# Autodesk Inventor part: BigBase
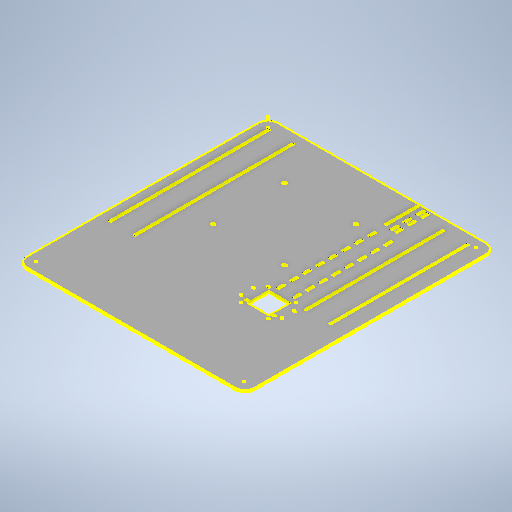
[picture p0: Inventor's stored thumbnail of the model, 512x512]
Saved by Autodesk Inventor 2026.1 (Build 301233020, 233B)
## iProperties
Created: 2026-10
Part Number: BigBase
Material: Generic
Document SubType Name: Modeling
Designer: hp
Density: 1 g/cm^3
Appearance: Default
Author: hp
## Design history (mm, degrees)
sketch "BigBaseSketch"
  geometry: L1 (0, 0)-(1200, 0); L2 (1200, 0)-(1200, 700); L3 (1200, 700)-(0, 700); L4 (0, 700)-(0, 0); L5 (378, 191.5)-(141, 191.5); L6 (141, 191.5)-(141, 428.5); L7 (141, 428.5)-(378, 428.5); L8 (378, 428.5)-(378, 191.5); L9 (378, 191.5)-(141, 428.5); L10 (141, 191.5)-(378, 428.5); L11 (259.5, 191.5)-(259.5, 428.5); L12 (378, 310)-(141, 310); L13 (141, 310)-(378, 310); C1 r 5 at (150, 200.5); C2 r 5 at (150, 419.5); C3 r 5 at (369, 200.5); C4 r 5 at (369, 419.5); 1 further point
  constraints: 26 end point, 5 midpoint, 5 symmetric about line, 4 centre point, 4 parallel, 2 horizontal, 2 perpendicular, 1 point on line, 3 other
  dimensions: "d0" = 1200 distance of L3.end L2.end; "d236" = 237 distance of L6.end L7.end; "d237" = 237 distance of L5.end L6.end; "d242" = 10 diameter of C1; "d243" = 9 distance from line of L5 C1.centre; "d245" = 150 distance from line of L4 C1.centre; "d252" = 700 distance of L3.end L1.start; "d253" = 40 vertical distance of point (0, 350) L12.end
extrude "Extrusion2" new body sketch "BigBaseSketch" distance "d14" = 5; taper "d15" = 0 deg
sketch "Sketch3"
  geometry: L1 (31, -10)-(31, 630); L2 (31, 106.5)-(521, 106.5); L3 (521, 106.5)-(521, 111.5); L4 (521, 111.5)-(31, 111.5); L5 (31, 111.5)-(31, 106.5); L6 (31, 31.5)-(521, 31.5); L7 (521, 31.5)-(521, 36.5); L8 (521, 36.5)-(31, 36.5); L9 (31, 36.5)-(31, 31.5); L10 (31, 568.5)-(456, 568.5); L11 (456, 568.5)-(456, 573.5); L12 (456, 573.5)-(31, 573.5); L13 (31, 573.5)-(31, 568.5); L14 (31, 643.5)-(456, 643.5); L15 (456, 648.5)-(31, 648.5); L16 (456, 643.5)-(456, 648.5); L17 (31, 648.5)-(31, 643.5); L18 (378, 191.5)-(141, 191.5) reference; L19 (141, 191.5)-(141, 428.5) reference; L20 (141, 428.5)-(378, 428.5) reference; L21 (378, 428.5)-(378, 191.5) reference; L22 (259.5, 191.5)-(259.5, 428.5) reference; L23 (0, 700)-(0, 0) reference; L24 (131, 468.5)-(461, 468.5); L25 (461, 468.5)-(461, 523.5); L26 (461, 523.5)-(131, 523.5); L27 (131, 523.5)-(131, 468.5); L28 (131, 468.5)-(461, 468.5); L29 (461, 468.5)-(461, 473.5); L30 (461, 473.5)-(131, 473.5); L31 (131, 473.5)-(131, 468.5); L32 (131, 523.5)-(461, 523.5); L33 (461, 523.5)-(461, 518.5); L34 (461, 518.5)-(131, 518.5); L35 (131, 518.5)-(131, 523.5); 3 further points; 2 other entities
  constraints: 58 end point, 14 parallel, 7 horizontal, 7 perpendicular, 4 collinear, 2 midpoint, 2 point on line, 1 horizontal alignment, 2 other
  dimensions: "d64" = 640 distance of L1.end L1.start; "d129" = 490 distance of L4.end L3.end; "d130" = 5 distance of L3.end L2.end; "d133" = 490 distance of L8.end L7.end (derived); "d134" = 5 distance of L7.end L6.end; "d135" = 70 distance between parallel lines of L2 L8; "d138" = 425 distance of L12.end L11.end; "d139" = 5 distance of L11.end L10.end; "d140" = 425 distance of L15.end L15.start (derived); "d141" = 5 distance of L15.start L14.end; "d144" = 70 distance between parallel lines of L12 L14; "d248" = 80 distance between parallel lines of L4 L18; "d249" = 140 distance between parallel lines of L20 L10; "d251" = 31 distance between parallel lines of L1 L23; "d259" = 330 distance of L26.end L25.end; "d260" = 55 distance of L25.end L24.end; "d261" = 40 distance between parallel lines of L20 L24; "d262" = 5 distance between parallel lines of L11 L25; "d263" = 5 distance of L29.end L28.end; "d264" = 5 distance of L32.end L33.end
extrude "Extrusion3" cut sketch "Sketch3" extent not by distance; stored distance "d101" = 0; taper "d102" = 0 deg
sketch "Sketch20"
  geometry: 4 further points
hole "Hole8" sketch "Sketch20" at (-477, 433.5), (-515, 433.5), (-477, 558.5), (-515, 558.5) diameter "d331" = 4.5; stored, may be unused: countersink angle "d335" = 90 deg, drill point angle "d337" = 0 deg; dims "d332" = 6, "d333" = 4, "d334" = 2, "d336" = 8
sketch "Sketch4"
  geometry: L1 (526, 463.5)-(526, 528.5); L2 (526, 528.5)-(461, 528.5); L3 (461, 528.5)-(461, 463.5); L4 (461, 463.5)-(526, 463.5); L5 (378, 428.5)-(378, 191.5) reference; L6 (378, 191.5)-(141, 191.5) reference; L7 (461, 468.5)-(461, 523.5) reference; 1 further point
  constraints: 8 end point, 2 parallel, 1 perpendicular
  dimensions: "d119" = 65 distance of L3.end L2.end; "d120" = 65 distance of L2.end L1.end; "d330" = 83 distance between parallel lines of L5 L3
extrude "Extrusion4" cut sketch "Sketch4" extent not by distance; stored distance "d112" = 0; taper "d113" = 0 deg
fillet "Fillet1" dims "d147" = 30
extrude "Extrusion7" cut sketch "BigBaseSketch" distance "d246" = 5; taper "d247" = 0 deg
sketch "Sketch16"
  geometry: L1 (131, 468.5)-(461, 468.5) reference; L2 (461, 473.5)-(131, 473.5) reference; L3 (461, 518.5)-(131, 518.5) reference; L4 (131, 523.5)-(461, 523.5) reference; L5 (131, 523.5)-(131, 468.5) reference; L6 (461, 468.5)-(461, 523.5) reference; L7 (141, 468.5)-(161, 468.5); L8 (161, 468.5)-(161, 473.5); L9 (161, 473.5)-(141, 473.5); L10 (141, 473.5)-(141, 468.5); L11 (141, 518.5)-(161, 518.5); L12 (161, 518.5)-(161, 523.5); L13 (161, 523.5)-(141, 523.5); L14 (141, 523.5)-(141, 518.5); L15 (181, 473.5)-(181, 468.5); L16 (181, 468.5)-(201, 468.5); L17 (201, 473.5)-(181, 473.5); L18 (201, 468.5)-(201, 473.5); L19 (181, 518.5)-(201, 518.5); L20 (181, 523.5)-(181, 518.5); L21 (201, 518.5)-(201, 523.5); L22 (201, 523.5)-(181, 523.5); L23 (221, 473.5)-(221, 468.5); L24 (221, 468.5)-(241, 468.5); L25 (241, 473.5)-(221, 473.5); L26 (241, 468.5)-(241, 473.5); L27 (221, 518.5)-(241, 518.5); L28 (221, 523.5)-(221, 518.5); L29 (241, 518.5)-(241, 523.5); L30 (241, 523.5)-(221, 523.5); L31 (261, 473.5)-(261, 468.5); L32 (261, 468.5)-(281, 468.5); L33 (281, 473.5)-(261, 473.5); L34 (281, 468.5)-(281, 473.5); L35 (261, 518.5)-(281, 518.5); L36 (261, 523.5)-(261, 518.5); L37 (281, 518.5)-(281, 523.5); L38 (281, 523.5)-(261, 523.5); L39 (301, 473.5)-(301, 468.5); L40 (301, 468.5)-(321, 468.5); L41 (321, 473.5)-(301, 473.5); L42 (321, 468.5)-(321, 473.5); L43 (301, 518.5)-(321, 518.5); L44 (301, 523.5)-(301, 518.5); L45 (321, 518.5)-(321, 523.5); L46 (321, 523.5)-(301, 523.5); L47 (341, 473.5)-(341, 468.5); L48 (341, 468.5)-(361, 468.5); L49 (361, 473.5)-(341, 473.5); L50 (361, 468.5)-(361, 473.5); L51 (341, 518.5)-(361, 518.5); L52 (341, 523.5)-(341, 518.5); L53 (361, 518.5)-(361, 523.5); L54 (361, 523.5)-(341, 523.5); L55 (381, 473.5)-(381, 468.5); L56 (381, 468.5)-(401, 468.5); L57 (401, 473.5)-(381, 473.5); L58 (401, 468.5)-(401, 473.5); L59 (381, 518.5)-(401, 518.5); L60 (381, 523.5)-(381, 518.5); L61 (401, 518.5)-(401, 523.5); L62 (401, 523.5)-(381, 523.5); L63 (421, 473.5)-(421, 468.5); L64 (421, 468.5)-(441, 468.5)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; 1 further point
  constraints: 128 end point, 4 parallel, 4 point on line, 3 horizontal, 2 perpendicular, 1 collinear, 112 other
  dimensions: "d274" = 20 distance of L9.end L8.end; "d275" = 10 distance between parallel lines of L5 L10; "d276" = 20 distance of L13.end L12.end; "d279" = 40 distance of L7.start L15.end
extrude "Extrusion8" cut sketch "Sketch16" distance "d284" = 5; taper "d285" = 0 deg
sketch "Sketch17"
  geometry: L1 (461, 528.5)-(526, 528.5) reference; L2 (461, 463.5)-(461, 528.5) reference; L3 (526, 528.5)-(526, 463.5) reference; L4 (526, 463.5)-(461, 463.5) reference; L5 (1170, 700)-(30, 700) reference; L6 (461, 700)-(526, 700); L7 (526, 700)-(526, 800); L8 (526, 800)-(461, 800); L9 (461, 800)-(461, 700); L10 (491.3, 590)-(498.5, 590); L11 (498.5, 590)-(498.5, 767); L12 (498.5, 767)-(491.3, 767); L13 (491.3, 767)-(491.3, 590); L14 (0, 492.4)-(121, 492.4); L15 (121, 492.4)-(121, 499.6); L16 (121, 499.6)-(0, 499.6); L17 (0, 499.6)-(0, 492.4); L18 (131, 523.5)-(131, 468.5) reference; L19 (0, 670)-(0, 30) reference; L20 (0, 499.6)-(121, 499.6); L21 (121, 499.6)-(121, 505.6); L22 (121, 505.6)-(0, 505.6); L23 (0, 505.6)-(0, 499.6); L24 (0, 492.4)-(121, 492.4); L25 (121, 492.4)-(121, 486.4); L26 (121, 486.4)-(0, 486.4); L27 (0, 486.4)-(0, 492.4); 6 further points
  constraints: 40 end point, 10 parallel, 5 horizontal, 5 perpendicular, 4 midpoint, 3 point on line, 1 collinear, 1 horizontal alignment
  dimensions: "d288" = 100 distance of L7.end L6.end; "d291" = 7.2 distance of L12.end L11.end; "d294" = 33 distance between parallel lines of L8 L12; "d295" = 210 distance from line of point (493.5, 800) L10; "d298" = 31.1 distance from line of L3 point (494.9, 590) (derived); "d306" = 7.2 distance of L15.end L14.end; "d307" = 10 distance of point (131, 496) point (121, 496); "d308" = 6 distance of L21.end L20.end; "d309" = 6 distance of L24.end L25.end (derived)
sketch "Sketch19"
  geometry: L1 (0, 670)-(0, 30) reference; L2 (121, 486.4)-(0, 486.4) reference; L3 (121, 505.6)-(0, 505.6) reference; L4 (121, 499.6)-(0, 499.6) reference; L5 (0, 492.4)-(121, 492.4) reference; L6 (121, 492.4)-(121, 486.4) reference; L7 (121, 499.6)-(121, 505.6) reference; L8 (10, 486.4)-(30, 486.4); L9 (30, 486.4)-(30, 492.4); L10 (30, 492.4)-(10, 492.4); L11 (10, 492.4)-(10, 486.4); L12 (10, 499.6)-(30, 499.6); L13 (30, 499.6)-(30, 505.6); L14 (30, 505.6)-(10, 505.6); L15 (10, 505.6)-(10, 499.6); L16 (10.1, 486.4)-(29.9, 486.4); L17 (29.9, 486.4)-(29.9, 492.4); L18 (29.9, 492.4)-(10.1, 492.4); L19 (10.1, 492.4)-(10.1, 486.4); L20 (10.1, 499.6)-(29.9, 499.6); L21 (29.9, 499.6)-(29.9, 505.6); L22 (29.9, 505.6)-(10.1, 505.6); L23 (10.1, 505.6)-(10.1, 499.6); L24 (50.1, 492.4)-(50.1, 486.4); L25 (50.1, 486.4)-(69.9, 486.4); L26 (50, 492.4)-(50, 486.4); L27 (50, 486.4)-(70, 486.4); L28 (69.9, 499.6)-(69.9, 505.6); L29 (70, 499.6)-(70, 505.6); L30 (69.9, 492.4)-(50.1, 492.4); L31 (70, 492.4)-(50, 492.4); L32 (50.1, 499.6)-(69.9, 499.6); L33 (50, 499.6)-(70, 499.6); L34 (69.9, 505.6)-(50.1, 505.6); L35 (70, 505.6)-(50, 505.6); L36 (50.1, 505.6)-(50.1, 499.6); L37 (50, 505.6)-(50, 499.6); L38 (69.9, 486.4)-(69.9, 492.4); L39 (70, 486.4)-(70, 492.4); L40 (90.1, 492.4)-(90.1, 486.4); L41 (90.1, 486.4)-(109.9, 486.4); L42 (90, 492.4)-(90, 486.4); L43 (90, 486.4)-(110, 486.4); L44 (109.9, 499.6)-(109.9, 505.6); L45 (110, 499.6)-(110, 505.6); L46 (109.9, 492.4)-(90.1, 492.4); L47 (110, 492.4)-(90, 492.4); L48 (90.1, 499.6)-(109.9, 499.6); L49 (90, 499.6)-(110, 499.6); L50 (109.9, 505.6)-(90.1, 505.6); L51 (110, 505.6)-(90, 505.6); L52 (90.1, 505.6)-(90.1, 499.6); L53 (90, 505.6)-(90, 499.6); L54 (109.9, 486.4)-(109.9, 492.4); L55 (110, 486.4)-(110, 492.4); 13 further points
  constraints: 96 end point, 8 parallel, 8 point on line, 5 horizontal, 4 midpoint, 4 perpendicular, 3 collinear, 2 coincident, 71 other
  dimensions: "d310" = 20 distance of L10.end L9.end; "d311" = 10 distance between parallel lines of L1 L11; "d321" = 19.8 distance of L18.end L17.end; "d322" = 19.8 distance of L22.end L21.end; "d325" = 40 distance of point (20, 492.4) point (60, 492.4)
extrude "Extrusion11" cut sketch "Sketch19" stored distance "d319" = 10; taper "d320" = 0 deg
sketch "Sketch21"
  geometry: L1 (1170, 700)-(30, 700) reference; L2 (1201.62, 0)-(771, 0); L3 (771, 0)-(771, 700); L4 (771, 700)-(1201.62, 700); L5 (1201.62, 700)-(1201.62, 0); L6 (521, 111.5)-(521, 106.5) reference; 2 further points
  constraints: 8 end point, 2 parallel, 1 horizontal, 1 perpendicular, 1 point on line
  dimensions: "d340" = 250 distance between parallel lines of L3 L6
extrude "Extrusion12" cut sketch "Sketch21" distance "d338" = 10; taper "d339" = 0 deg
fillet "Fillet2" dims "d341" = 30
sketch "Sketch22"
  geometry: L1 (5, 464.5)-(105, 464.5); L2 (105, 464.5)-(105, 469.5); L3 (105, 469.5)-(5, 469.5); L4 (5, 469.5)-(5, 464.5); L5 (0, 670)-(0, 30) reference; L6 (29.9, 486.4)-(10.1, 486.4) reference; 2 further points
  constraints: 8 end point, 2 parallel, 1 horizontal, 1 midpoint, 1 perpendicular
  dimensions: "d342" = 100 distance of L3.end L2.end; "d343" = 5 distance of L2.end L1.end; "d344" = 5 distance from line of L5 point (5, 467); "d345" = 16.9 distance between parallel lines of L6 L3
extrude "Extrusion13" cut sketch "Sketch22" distance "d346" = 5; taper "d347" = 0 deg
sketch "Sketch23"
  geometry: 4 further points
hole "Hole9" sketch "Sketch23" at (536, 538.5), (451, 538.5), (451, 453.5), (536, 453.5) diameter "d348" = 4.5; stored, may be unused: countersink angle "d352" = 90 deg, drill point angle "d354" = 0 deg; dims "d349" = 6, "d350" = 4, "d351" = 2, "d353" = 8
sketch "Sketch24"
  geometry: L1 (-105, 469.5)-(-5, 469.5) reference; L2 (-5, 469.5)-(-5, 464.5) reference; L3 (-5, 464.5)-(-105, 464.5) reference; L4 (-105, 464.5)-(-105, 469.5) reference; L5 (-771, 670)-(-771, 30) reference; L6 (-30, 0)-(-741, 0) reference; L7 (0, 670)-(0, 30) reference; L8 (-741, 700)-(-30, 700) reference; L9 (-69.9, 505.6)-(-50.1, 505.6) reference; L10 (-50.1, 505.6)-(-50.1, 499.6) reference; L11 (-50.1, 499.6)-(-69.9, 499.6) reference; L12 (-69.9, 499.6)-(-69.9, 505.6) reference; L13 (-109.9, 499.6)-(-109.9, 505.6) reference; L14 (-109.9, 505.6)-(-90.1, 505.6) reference; L15 (-90.1, 505.6)-(-90.1, 499.6) reference; L16 (-90.1, 499.6)-(-109.9, 499.6) reference; L17 (-90.1, 486.4)-(-109.9, 486.4) reference; L18 (-109.9, 486.4)-(-109.9, 492.4) reference; L19 (-109.9, 492.4)-(-90.1, 492.4) reference; L20 (-90.1, 492.4)-(-90.1, 486.4) reference; L21 (-10.1, 499.6)-(-29.9, 499.6) reference; L22 (-29.9, 499.6)-(-29.9, 505.6) reference; L23 (-29.9, 505.6)-(-10.1, 505.6) reference; L24 (-10.1, 505.6)-(-10.1, 499.6) reference; L25 (-50.1, 486.4)-(-69.9, 486.4) reference; L26 (-69.9, 486.4)-(-69.9, 492.4) reference; L27 (-69.9, 492.4)-(-50.1, 492.4) reference; L28 (-50.1, 492.4)-(-50.1, 486.4) reference; L29 (-10.1, 486.4)-(-29.9, 486.4) reference; L30 (-29.9, 486.4)-(-29.9, 492.4) reference; L31 (-29.9, 492.4)-(-10.1, 492.4) reference; L32 (-10.1, 492.4)-(-10.1, 486.4) reference; L33 (-321, 468.5)-(-321, 473.5) reference; L34 (-321, 473.5)-(-301, 473.5) reference; L35 (-301, 473.5)-(-301, 468.5) reference; L36 (-301, 468.5)-(-321, 468.5) reference; L37 (-361, 468.5)-(-361, 473.5) reference; L38 (-361, 473.5)-(-341, 473.5) reference; L39 (-341, 473.5)-(-341, 468.5) reference; L40 (-341, 468.5)-(-361, 468.5) reference; L41 (-401, 468.5)-(-401, 473.5) reference; L42 (-401, 473.5)-(-381, 473.5) reference; L43 (-381, 473.5)-(-381, 468.5) reference; L44 (-381, 468.5)-(-401, 468.5) reference; L45 (-441, 468.5)-(-441, 473.5) reference; L46 (-441, 473.5)-(-421, 473.5) reference; L47 (-421, 473.5)-(-421, 468.5) reference; L48 (-421, 468.5)-(-441, 468.5) reference; L49 (-161, 523.5)-(-141, 523.5) reference; L50 (-141, 523.5)-(-141, 518.5) reference; L51 (-141, 518.5)-(-161, 518.5) reference; L52 (-161, 518.5)-(-161, 523.5) reference; L53 (-201, 523.5)-(-181, 523.5) reference; L54 (-181, 523.5)-(-181, 518.5) reference; L55 (-181, 518.5)-(-201, 518.5) reference; L56 (-201, 518.5)-(-201, 523.5) reference; L57 (-241, 523.5)-(-221, 523.5) reference; L58 (-221, 523.5)-(-221, 518.5) reference; L59 (-221, 518.5)-(-241, 518.5) reference; L60 (-241, 518.5)-(-241, 523.5) reference; L61 (-281, 523.5)-(-261, 523.5) reference; L62 (-261, 523.5)-(-261, 518.5) reference; L63 (-261, 518.5)-(-281, 518.5) reference; L64 (-281, 518.5)-(-281, 523.5) reference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; C1 r 2.25 at (-536, 453.5) reference; C2 r 2.25 at (-451, 453.5) reference; C3 r 2.25 at (-451, 538.5) reference; C4 r 2.25 at (-536, 538.5) reference; C5 r 5 at (-369, 200.5) reference; C6 r 5 at (-150, 419.5) reference; C7 r 5 at (-369, 419.5) reference; C8 r 5 at (-150, 200.5) reference; C9 r 2.25 at (-515, 558.5) reference; C10 r 2.25 at (-477, 558.5) reference; C11 r 2.25 at (-515, 433.5) reference; C12 r 2.25 at (-477, 433.5) reference; A1 r 30 centre (-741, 670) between (-741, 700) and (-771, 670) reference; A2 r 30 centre (-741, 30) between (-771, 30) and (-741, 0) reference; A3 r 30 centre (-30, 30) between (-30, 0) and (0, 30) reference; A4 r 30 centre (-30, 670) between (0, 670) and (-30, 700) reference; 1 further point
  node "Projected Loop2"
sketch "Sketch25"
  geometry: L1 (526, 528.5)-(526, 463.5) reference; L2 (526, 463.5)-(461, 463.5) reference; L3 (461, 528.5)-(526, 528.5) reference; L4 (461, 463.5)-(461, 528.5) reference; L5 (521, 461)-(516, 461); L6 (516, 461)-(516, 451.2); L7 (516, 451.2)-(521, 451.2); L8 (521, 451.2)-(521, 461); L9 (516, 531)-(521, 531); L10 (521, 531)-(521, 540.8); L11 (521, 540.8)-(516, 540.8); L12 (516, 540.8)-(516, 531); 1 further point
  constraints: 16 end point, 4 parallel, 2 horizontal, 2 perpendicular, 2 point on line
  dimensions: "d355" = 5 distance of L7.end L6.end; "d356" = 9.8 distance of L6.end L5.end; "d357" = 9.8 distance of L10.end L9.end; "d358" = 5 distance between parallel lines of L1 L10; "d359" = 2.5 distance between parallel lines of L3 L9; "d360" = 2.5 distance between parallel lines of L5 L2 (derived)
extrude "Extrusion14" cut sketch "Sketch25" stored distance "d361" = 5; taper "d362" = 0 deg
sketch "Sketch26"
  geometry: L1 (521, 540.8)-(521, 531) reference; L2 (521, 531)-(516, 531) reference; L3 (516, 531)-(516, 540.8) reference; L4 (516, 540.8)-(521, 540.8) reference; L5 (516, 461)-(521, 461) reference; L6 (521, 461)-(521, 451.2) reference; L7 (521, 451.2)-(516, 451.2) reference; L8 (516, 451.2)-(516, 461) reference; L9 (5, 469.5)-(105, 469.5) reference; L10 (105, 469.5)-(105, 464.5) reference; L11 (105, 464.5)-(5, 464.5) reference; L12 (5, 464.5)-(5, 469.5) reference; L13 (31, 573.5)-(456, 573.5) reference; L14 (456, 573.5)-(456, 568.5) reference; L15 (456, 568.5)-(31, 568.5) reference; L16 (31, 568.5)-(31, 573.5) reference; L17 (31, 111.5)-(521, 111.5) reference; L18 (521, 111.5)-(521, 106.5) reference; L19 (521, 106.5)-(31, 106.5) reference; L20 (31, 106.5)-(31, 111.5) reference; L21 (31, 648.5)-(456, 648.5) reference; L22 (456, 648.5)-(456, 643.5) reference; L23 (456, 643.5)-(31, 643.5) reference; L24 (31, 643.5)-(31, 648.5) reference; L25 (31, 36.5)-(521, 36.5) reference; L26 (521, 36.5)-(521, 31.5) reference; L27 (521, 31.5)-(31, 31.5) reference; L28 (31, 31.5)-(31, 36.5) reference; L29 (461, 463.5)-(461, 528.5) reference; L30 (461, 528.5)-(526, 528.5) reference; L31 (526, 528.5)-(526, 463.5) reference; L32 (526, 463.5)-(461, 463.5) reference; L33 (741, 700)-(30, 700) reference; L34 (0, 670)-(0, 30) reference; L35 (30, 0)-(741, 0) reference; L36 (771, 30)-(771, 670) reference; L37 (421, 523.5)-(441, 523.5) reference; L38 (441, 523.5)-(441, 518.5) reference; L39 (441, 518.5)-(421, 518.5) reference; L40 (421, 518.5)-(421, 523.5) reference; L41 (301, 523.5)-(321, 523.5) reference; L42 (321, 523.5)-(321, 518.5) reference; L43 (321, 518.5)-(301, 518.5) reference; L44 (301, 518.5)-(301, 523.5) reference; L45 (341, 523.5)-(361, 523.5) reference; L46 (361, 523.5)-(361, 518.5) reference; L47 (361, 518.5)-(341, 518.5) reference; L48 (341, 518.5)-(341, 523.5) reference; L49 (381, 523.5)-(401, 523.5) reference; L50 (401, 523.5)-(401, 518.5) reference; L51 (401, 518.5)-(381, 518.5) reference; L52 (381, 518.5)-(381, 523.5) reference; L53 (141, 473.5)-(161, 473.5) reference; L54 (161, 473.5)-(161, 468.5) reference; L55 (161, 468.5)-(141, 468.5) reference; L56 (141, 468.5)-(141, 473.5) reference; L57 (201, 473.5)-(201, 468.5) reference; L58 (201, 468.5)-(181, 468.5) reference; L59 (181, 468.5)-(181, 473.5) reference; L60 (181, 473.5)-(201, 473.5) reference; L61 (241, 473.5)-(241, 468.5) reference; L62 (241, 468.5)-(221, 468.5) reference; L63 (221, 468.5)-(221, 473.5) reference; L64 (221, 473.5)-(241, 473.5) reference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; C1 r 2.25 at (536, 453.5) reference; C2 r 2.25 at (451, 453.5) reference; C3 r 2.25 at (451, 538.5) reference; C4 r 2.25 at (536, 538.5) reference; C5 r 2.25 at (477, 433.5) reference; C6 r 2.25 at (515, 433.5) reference; C7 r 2.25 at (477, 558.5) reference; C8 r 2.25 at (515, 558.5) reference; C9 r 5 at (150, 200.5) reference; C10 r 5 at (369, 419.5) reference; C11 r 5 at (150, 419.5) reference; C12 r 5 at (369, 200.5) reference; A1 r 30 centre (741, 670) between (771, 670) and (741, 700) reference; A2 r 30 centre (30, 670) between (30, 700) and (0, 670) reference; A3 r 30 centre (30, 30) between (0, 30) and (30, 0) reference; A4 r 30 centre (741, 30) between (741, 0) and (771, 30) reference; 1 further point
  node "Projected Loop3"
body "Solid2"
node "Sketch Rectangular Pattern6" dims "d279" = 40, "d282" = 10
node "Sketch Rectangular Pattern8" dims "d325" = 40, "d328" = 10
other parameters: "d110" = 63
